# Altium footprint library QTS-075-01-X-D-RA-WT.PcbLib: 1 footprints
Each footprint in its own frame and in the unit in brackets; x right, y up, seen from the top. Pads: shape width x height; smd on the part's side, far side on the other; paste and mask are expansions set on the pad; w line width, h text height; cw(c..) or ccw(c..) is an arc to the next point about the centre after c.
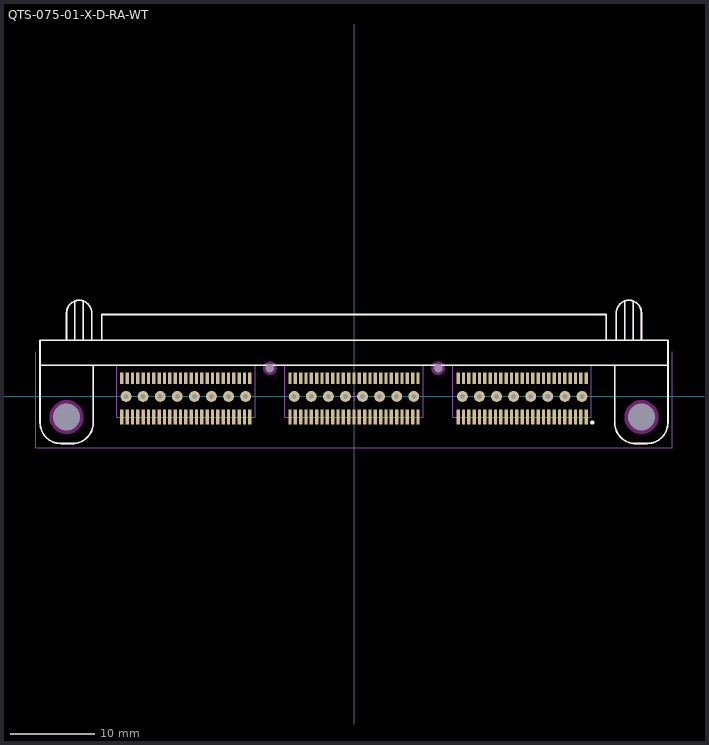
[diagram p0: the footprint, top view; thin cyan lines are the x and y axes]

## QTS-075-01-X-D-RA-WT [mm] "0.635mm pitch, 150 pin, high speed terminal strip; r/a, w/weld tabs"
height 9.42
pads (178):
  rect 0.4x1.8 smd mask+0: 1(27.623,-2.451) 3(26.988,-2.451) 5(26.353,-2.451) 7(25.718,-2.451) 9(25.083,-2.451) 11(24.448,-2.451) 13(23.813,-2.451) 15(23.178,-2.451) 17(22.543,-2.451) 19(21.908,-2.451) 21(21.273,-2.451) 23(20.638,-2.451) 25(20.003,-2.451) 27(19.368,-2.451) 29(18.733,-2.451) 31(18.098,-2.451) 33(17.463,-2.451) 35(16.828,-2.451) 37(16.193,-2.451) 39(15.558,-2.451) 41(14.923,-2.451) 43(14.288,-2.451) 45(13.653,-2.451) 47(13.018,-2.451) 49(12.383,-2.451) 51(7.62,-2.451) 53(6.985,-2.451) 55(6.35,-2.451) 57(5.715,-2.451) 59(5.08,-2.451) 61(4.445,-2.451) 63(3.81,-2.451) 65(3.175,-2.451) 67(2.54,-2.451) 69(1.905,-2.451) 71(1.27,-2.451) 73(0.635,-2.451) 75(0,-2.451) 77(-0.635,-2.451) 79(-1.27,-2.451) 81(-1.905,-2.451) 83(-2.54,-2.451) 85(-3.175,-2.451) 87(-3.81,-2.451) 89(-4.445,-2.451) 91(-5.08,-2.451) 93(-5.715,-2.451) 95(-6.35,-2.451) 97(-6.985,-2.451) 99(-7.62,-2.451) 101(-12.383,-2.451) 103(-13.018,-2.451) 105(-13.653,-2.451) 107(-14.288,-2.451) 109(-14.923,-2.451) 111(-15.558,-2.451) 113(-16.193,-2.451) 115(-16.828,-2.451) 117(-17.463,-2.451) 119(-18.098,-2.451) 121(-18.733,-2.451) 123(-19.368,-2.451) 125(-20.003,-2.451) 127(-20.638,-2.451) 129(-21.273,-2.451) 131(-21.908,-2.451) 133(-22.543,-2.451) 135(-23.178,-2.451) 137(-23.813,-2.451) 139(-24.448,-2.451) 141(-25.083,-2.451) 143(-25.718,-2.451) 145(-26.353,-2.451) 147(-26.988,-2.451) 149(-27.623,-2.451)
  rect 0.4x1.4 smd mask+0: 2(27.623,2.159) 4(26.988,2.159) 6(26.353,2.159) 8(25.718,2.159) 10(25.083,2.159) 12(24.448,2.159) 14(23.813,2.159) 16(23.178,2.159) 18(22.543,2.159) 20(21.908,2.159) 22(21.273,2.159) 24(20.638,2.159) 26(20.003,2.159) 28(19.368,2.159) 30(18.733,2.159) 32(18.098,2.159) 34(17.463,2.159) 36(16.828,2.159) 38(16.193,2.159) 40(15.558,2.159) 42(14.923,2.159) 44(14.288,2.159) 46(13.653,2.159) 48(13.018,2.159) 50(12.383,2.159) 52(7.62,2.159) 54(6.985,2.159) 56(6.35,2.159) 58(5.715,2.159) 60(5.08,2.159) 62(4.445,2.159) 64(3.81,2.159) 66(3.175,2.159) 68(2.54,2.159) 70(1.905,2.159) 72(1.27,2.159) 74(0.635,2.159) 76(0,2.159) 78(-0.635,2.159) 80(-1.27,2.159) 82(-1.905,2.159) 84(-2.54,2.159) 86(-3.175,2.159) 88(-3.81,2.159) 90(-4.445,2.159) 92(-5.08,2.159) 94(-5.715,2.159) 96(-6.35,2.159) 98(-6.985,2.159) 100(-7.62,2.159) 102(-12.383,2.159) 104(-13.018,2.159) 106(-13.653,2.159) 108(-14.288,2.159) 110(-14.923,2.159) 112(-15.558,2.159) 114(-16.193,2.159) 116(-16.828,2.159) 118(-17.463,2.159) 120(-18.098,2.159) 122(-18.733,2.159) 124(-19.368,2.159) 126(-20.003,2.159) 128(-20.638,2.159) 130(-21.273,2.159) 132(-21.908,2.159) 134(-22.543,2.159) 136(-23.178,2.159) 138(-23.813,2.159) 140(-24.448,2.159) 142(-25.083,2.159) 144(-25.718,2.159) 146(-26.353,2.159) 148(-26.988,2.159) 150(-27.623,2.159)
  round 1.3 hole 0.6 mask+0: 151(27.114,0) 152(25.082,0) 153(23.05,0) 154(21.018,0) 155(18.986,0) 156(16.954,0) 157(14.922,0) 158(12.89,0) 159(7.111,0) 160(5.079,0) 161(3.047,0) 162(1.015,0) 163(-1.017,0) 164(-3.049,0) 165(-5.081,0) 166(-7.113,0) 167(-12.892,0) 168(-14.924,0) 169(-16.956,0) 170(-18.988,0) 171(-21.02,0) 172(-23.052,0) 173(-25.084,0) 174(-27.116,0)
  round 1 hole 3.2 unplated mask+0: 175(34.195,-2.451) 176(-34.195,-2.451)
  round 0.5 hole 1 unplated mask+0: 177(10.001,3.353) 178(-10.001,3.353)
Top Overlay:
  circle w0.25: c28.35,-3.1 r0.125
  lines w0.2: -37.35,3.693 -37.35,-3.126 ccw(c-34.85,-3.1) -34.867,-5.6 ; -34.869,-5.6 -33.519,-5.6 ccw(c-33.502,-3.098) -31,-3.125 ; -34.2,6.7 -34.2,9.943 cw(c-32.7,9.943) -31.2,9.943 -31.2,6.7 ; -33.2,6.7 -33.2,11.35 ; -32.2,6.7 -32.2,11.35 ; -31,-3.126 -31,3.693 ; -30,6.7 -30,9.75 30,9.75 30,6.7 ; 31,-3.126 31,3.7 ; 31,-3.125 ccw(c33.502,-3.098) 33.519,-5.6 34.869,-5.6 ; 31.2,6.7 31.2,9.943 cw(c32.7,9.943) 34.2,9.943 34.2,6.7 ; 32.2,6.7 32.2,11.35 ; 33.2,6.7 33.2,11.35 ; 34.867,-5.6 ccw(c34.85,-3.1) 37.35,-3.126 37.35,3.693 ; -37.35,3.7 -37.35,6.7 37.35,6.7 37.35,3.7 -37.35,3.7
Keep-Out Layer:
  pour cut-out: -9.195,3.353 -9.223,3.562 -9.303,3.756 -9.431,3.924 -9.599,4.052 -9.793,4.132 -10.002,4.16 -10.211,4.132 -10.405,4.052 -10.573,3.924 -10.701,3.756 -10.781,3.562 -10.809,3.353 -10.781,3.144 -10.701,2.95 -10.573,2.782 -10.405,2.654 -10.211,2.574 -10.002,2.546 -9.793,2.574 -9.599,2.654 -9.431,2.782 -9.303,2.95 -9.223,3.144
  pour cut-out: 10.809,3.353 10.781,3.562 10.701,3.756 10.573,3.924 10.405,4.052 10.211,4.132 10.002,4.16 9.793,4.132 9.599,4.052 9.431,3.924 9.303,3.756 9.223,3.562 9.195,3.353 9.223,3.144 9.303,2.95 9.431,2.782 9.599,2.654 9.793,2.574 10.002,2.546 10.211,2.574 10.405,2.654 10.573,2.782 10.701,2.95 10.781,3.144
  pour cut-out: 36.205,-2.451 36.166,-2.059 36.052,-1.682 35.866,-1.334 35.616,-1.03 35.312,-0.78 34.964,-0.594 34.587,-0.48 34.195,-0.441 33.803,-0.48 33.426,-0.594 33.078,-0.78 32.774,-1.03 32.524,-1.334 32.338,-1.682 32.224,-2.059 32.185,-2.451 32.224,-2.843 32.338,-3.22 32.524,-3.568 32.774,-3.872 33.078,-4.122 33.426,-4.308 33.803,-4.422 34.195,-4.461 34.587,-4.422 34.964,-4.308 35.312,-4.122 35.616,-3.872 35.866,-3.568 36.052,-3.22 36.166,-2.843
  pour cut-out: -32.184,-2.451 -32.223,-2.059 -32.337,-1.682 -32.523,-1.334 -32.773,-1.03 -33.077,-0.78 -33.425,-0.594 -33.802,-0.48 -34.194,-0.441 -34.586,-0.48 -34.963,-0.594 -35.311,-0.78 -35.615,-1.03 -35.865,-1.334 -36.051,-1.682 -36.165,-2.059 -36.204,-2.451 -36.165,-2.843 -36.051,-3.22 -35.865,-3.568 -35.615,-3.872 -35.311,-4.122 -34.963,-4.308 -34.586,-4.422 -34.194,-4.461 -33.802,-4.422 -33.425,-4.308 -33.077,-4.122 -32.773,-3.872 -32.523,-3.568 -32.337,-3.22 -32.223,-2.843
Mechanical 12:
  lines w0.001: -37.35,-3.1 -37.35,6.7 -30,6.7 -30,9.75 30,9.75 30,6.7 37.35,6.7 37.35,-3.1 ; -34.85,-5.6 -33.5,-5.6 ; -31,-3.1 -31,3.7 -28.25,3.7 -28.25,-2.5 -11.75,-2.5 -11.75,3.7 -8.25,3.7 -8.25,-2.5 8.25,-2.5 8.25,3.7 11.75,3.7 11.75,-2.5 28.25,-2.5 28.25,3.7 31,3.7 31,-3.1 ; 33.5,-5.6 34.85,-5.6
Mechanical 13:
  lines w0.1: -37.35,3.693 -37.35,-3.126 ccw(c-34.85,-3.1) -34.867,-5.6 ; -34.869,-5.6 -33.519,-5.6 ccw(c-33.502,-3.098) -31,-3.125 ; -34.2,6.7 -34.2,9.943 cw(c-32.7,9.943) -31.2,9.943 -31.2,6.7 ; -33.2,6.7 -33.2,11.35 ; -32.2,6.7 -32.2,11.35 ; -31,-3.126 -31,3.693 ; -30,6.7 -30,9.75 30,9.75 30,6.7 ; -28.25,3.7 -28.25,-2.5 -11.75,-2.5 -11.75,3.7 ; -8.25,3.7 -8.25,-2.5 8.25,-2.5 8.25,3.7 ; 11.75,3.7 11.75,-2.5 28.25,-2.5 28.25,3.7 ; 31,-3.126 31,3.7 ; 31,-3.125 ccw(c33.502,-3.098) 33.519,-5.6 34.869,-5.6 ; 31.2,6.7 31.2,9.943 cw(c32.7,9.943) 34.2,9.943 34.2,6.7 ; 32.2,6.7 32.2,11.35 ; 33.2,6.7 33.2,11.35 ; 34.867,-5.6 ccw(c34.85,-3.1) 37.35,-3.126 37.35,3.693 ; -37.35,3.7 -37.35,6.7 37.35,6.7 37.35,3.7 -37.35,3.7
  text ".Designator" at 0,0 h1.52
Mechanical 15:
  lines w0.05: -37.85,5.296 -37.85,-6.1 37.85,-6.1 37.85,5.296 ; -0.5,0 0.5,0 -0.5,0 ; 0,-0.5 0,0.5 0,-0.5
Mechanical 16:
  lines w0.001: -37.35,-3.1 ccw(c-34.85,-3.1) -34.85,-5.6 ; -33.5,-5.6 ccw(c-33.5,-3.1) -31,-3.1 ; 31,-3.1 ccw(c33.5,-3.1) 33.5,-5.6 ; 34.85,-5.6 ccw(c34.85,-3.1) 37.35,-3.1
